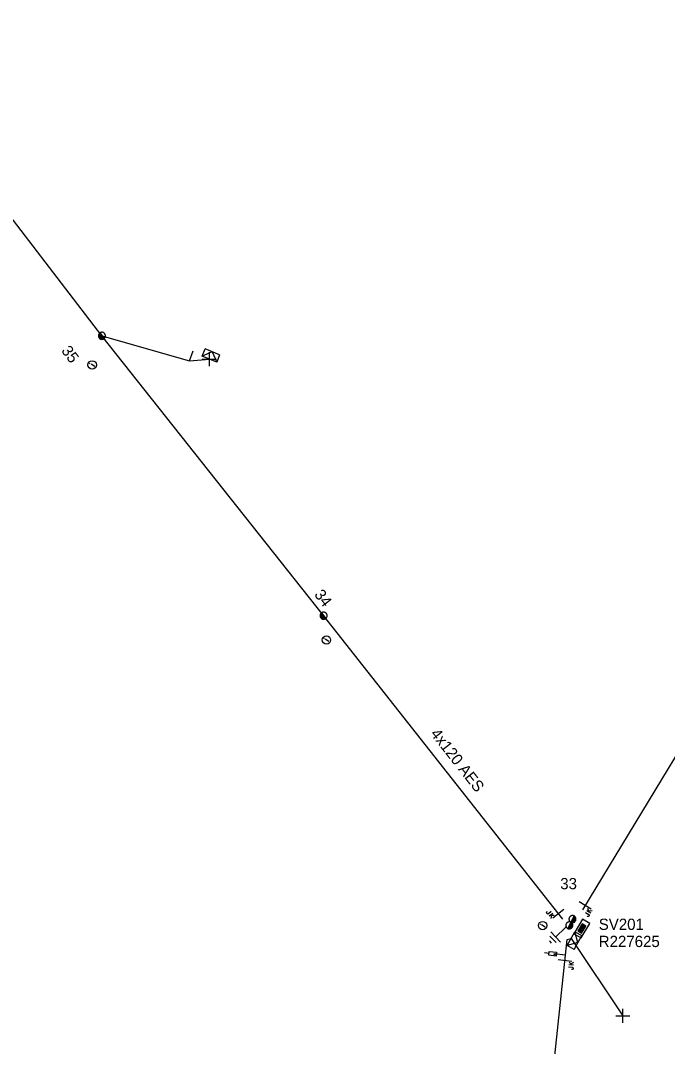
# Model space of a CAD drawing. Extents: x -544780 to -541582, y -1198995 to -1196551.
# Drawn here: x -543784.9 to -543727.4, y -1197085.7 to -1196994.5 of the extents above; entities that cross this region are included whole.
import ezdxf

# ---------------------------------------------------------------- set-up
doc = ezdxf.new("R2010")
doc.units = 0
for name, color, linetype in [('Vrstva 1', 7, 'Continuous'), ('Vrstva 10', 7, 'Continuous'), ('Vrstva 13', 7, 'Continuous'), ('Vrstva 14', 7, 'Continuous'), ('Vrstva 15', 7, 'Continuous'), ('Vrstva 16', 7, 'Continuous'), ('Vrstva 18', 7, 'Continuous'), ('Vrstva 2', 7, 'Continuous'), ('Vrstva 28', 7, 'Continuous'), ('Vrstva 29', 7, 'Continuous'), ('Vrstva 30', 7, 'Continuous'), ('Vrstva 31', 7, 'Continuous'), ('Vrstva 34', 7, 'Continuous'), ('Vrstva 36', 7, 'Continuous'), ('Vrstva 50', 7, 'Continuous'), ('Vrstva 51', 7, 'Continuous'), ('Vrstva 54', 7, 'Continuous'), ('Vrstva 59', 7, 'Continuous'), ('Vrstva 8', 7, 'Continuous'), ('Vrstva 9', 7, 'Continuous')]:
    doc.layers.add(name, color=color, linetype=linetype)

# ---------------------------------------------------------------- blocks, each defined once
blk = doc.blocks.new('NN440')
at = {"layer": 'Vrstva 2'}
for points in [[(0.63, 0), (0.63, 0.06), (0.62, 0.13), (0.6, 0.19), (0.58, 0.25), (0.55, 0.31), (0.51, 0.37), (0.47, 0.42), (0.42, 0.46), (0.37, 0.51), (0.32, 0.54), (0.26, 0.57), (0.2, 0.59), (0.13, 0.61), (0.07, 0.62), (0, 0.63), (-0.06, 0.62), (-0.13, 0.61), (-0.19, 0.59), (-0.26, 0.57), (-0.31, 0.54), (-0.37, 0.51), (-0.42, 0.46), (-0.47, 0.42), (-0.51, 0.37), (-0.54, 0.31), (-0.57, 0.25), (-0.6, 0.19), (-0.62, 0.13), (-0.63, 0.06), (-0.63, 0), (-0.63, -0.07), (-0.62, -0.14), (-0.6, -0.2), (-0.57, -0.26), (-0.54, -0.32), (-0.51, -0.37), (-0.47, -0.43), (-0.42, -0.47), (-0.37, -0.51), (-0.31, -0.55), (-0.26, -0.58), (-0.19, -0.6), (-0.13, -0.62), (-0.06, -0.63), (0, -0.63), (0.07, -0.63), (0.13, -0.62), (0.2, -0.6), (0.26, -0.58), (0.32, -0.55), (0.37, -0.51), (0.42, -0.47), (0.47, -0.43), (0.51, -0.37), (0.55, -0.32), (0.58, -0.26), (0.6, -0.2), (0.62, -0.14), (0.63, -0.07), (0.63, 0)], [(-0.63, 0), (0.63, 0)], [(-0.6, -0.18), (0.57, -0.18)], [(-0.51, -0.32), (0.5, -0.32)], [(-0.37, -0.47), (0.35, -0.47)]]:
    blk.add_lwpolyline(points, dxfattribs=at)
blk = doc.blocks.new('NN450')
at = {"layer": 'Vrstva 2'}
for points in [[(0, 0), (0, 0.07), (-0.01, 0.13), (-0.03, 0.19), (-0.05, 0.25), (-0.08, 0.31), (-0.12, 0.37), (-0.16, 0.42), (-0.21, 0.46), (-0.26, 0.51), (-0.31, 0.54), (-0.37, 0.57), (-0.43, 0.59), (-0.5, 0.61), (-0.56, 0.62), (-0.63, 0.62), (-0.69, 0.62), (-0.75, 0.61), (-0.82, 0.59), (-0.88, 0.57), (-0.94, 0.54), (-0.99, 0.51), (-1.04, 0.46), (-1.09, 0.42), (-1.13, 0.37), (-1.17, 0.31), (-1.2, 0.25), (-1.22, 0.19), (-1.24, 0.13), (-1.25, 0.07), (-1.25, 0), (-1.25, -0.07), (-1.24, -0.13), (-1.22, -0.19), (-1.2, -0.25), (-1.17, -0.31), (-1.13, -0.37), (-1.09, -0.42), (-1.04, -0.46), (-0.99, -0.51), (-0.94, -0.54), (-0.88, -0.57), (-0.82, -0.59), (-0.75, -0.61), (-0.69, -0.62), (-0.62, -0.63), (-0.56, -0.62), (-0.5, -0.61), (-0.43, -0.59), (-0.37, -0.57), (-0.31, -0.54), (-0.26, -0.51), (-0.21, -0.46), (-0.16, -0.42), (-0.12, -0.37), (-0.08, -0.31), (-0.05, -0.25), (-0.03, -0.19), (-0.01, -0.13), (0, -0.07), (0, 0)], [(1.25, 0), (1.25, 0.07), (1.24, 0.13), (1.22, 0.19), (1.2, 0.25), (1.17, 0.31), (1.13, 0.37), (1.09, 0.42), (1.04, 0.46), (0.99, 0.51), (0.94, 0.54), (0.88, 0.57), (0.82, 0.59), (0.75, 0.61), (0.69, 0.62), (0.62, 0.62), (0.56, 0.62), (0.5, 0.61), (0.43, 0.59), (0.37, 0.57), (0.31, 0.54), (0.26, 0.51), (0.21, 0.46), (0.16, 0.42), (0.12, 0.37), (0.08, 0.31), (0.05, 0.25), (0.03, 0.19), (0.01, 0.13), (0, 0.07), (0, 0), (0, -0.07), (0.01, -0.13), (0.03, -0.19), (0.05, -0.25), (0.08, -0.31), (0.12, -0.37), (0.16, -0.42), (0.21, -0.46), (0.26, -0.51), (0.31, -0.54), (0.37, -0.57), (0.43, -0.59), (0.5, -0.61), (0.56, -0.62), (0.63, -0.63), (0.69, -0.62), (0.75, -0.61), (0.82, -0.59), (0.88, -0.57), (0.94, -0.54), (0.99, -0.51), (1.04, -0.46), (1.09, -0.42), (1.13, -0.37), (1.17, -0.31), (1.2, -0.25), (1.22, -0.19), (1.24, -0.13), (1.25, -0.07), (1.25, 0)], [(-1.25, 0), (1.25, 0)], [(-1.23, -0.16), (-0.02, -0.16)], [(-1.16, -0.32), (-0.09, -0.32)], [(-1.03, -0.47), (-0.22, -0.47)], [(0.02, -0.16), (1.23, -0.16)], [(0.09, -0.32), (1.16, -0.32)], [(0.22, -0.47), (1.03, -0.47)]]:
    blk.add_lwpolyline(points, dxfattribs=at)
blk = doc.blocks.new('NN840')
at = {"layer": 'Vrstva 15'}
for points in [[(0.003, 0.619), (0.003, -0.631)], [(-0.745, -0.71), (-0.745, -0.66)], [(-0.73, -0.764), (-0.745, -0.71)], [(-0.657, -0.798), (-0.73, -0.764)], [(-0.627, -0.798), (-0.657, -0.798)], [(-0.558, -0.764), (-0.627, -0.798)], [(-0.538, -0.71), (-0.558, -0.764)], [(-0.538, -0.385), (-0.538, -0.71)], [(-0.332, -0.385), (-0.332, -0.798)], [(-0.332, -0.641), (-0.125, -0.385)], [(-0.263, -0.557), (-0.091, -0.798)]]:
    blk.add_lwpolyline(points, dxfattribs=at)
blk = doc.blocks.new('NN770')
at = {"layer": 'Vrstva 10'}
for p, q in [((0.002, 0.187), (0.002, 0.263)), ((0.002, -0.276), (0.002, 0.111))]:
    blk.add_line(p, q, dxfattribs=at)
blk.add_circle((0, -0.008), 0.375, dxfattribs=at)
blk = doc.blocks.new('NN800')
at = {"layer": 'Vrstva 1'}
for points in [[(-0.442, 0.442), (0.442, -0.442)], [(-0.442, -0.442), (0.442, 0.442)]]:
    blk.add_lwpolyline(points, dxfattribs=at)
blk = doc.blocks.new('NN820')
at = {"layer": 'Vrstva 13'}
for points in [[(-0.003, 0.004), (-0.003, -1.049)], [(-0.165, -0.813), (0.165, -0.813)], [(-0.165, -1.473), (-0.165, -0.813)], [(0.165, -0.813), (0.165, -1.473)], [(0.165, -1.473), (-0.165, -1.473)], [(-0.003, -1.049), (-0.062, -0.926)], [(-0.003, -1.049), (0.057, -0.926)], [(-0.003, -1.473), (-0.003, -1.871)]]:
    blk.add_lwpolyline(points, dxfattribs=at)
blk = doc.blocks.new('NN620')
at = {"layer": 'Vrstva 8'}
for points in [[(0.752, 0.004), (-0.748, 0.004)], [(-0.748, 0.004), (-0.748, -0.746)], [(0.752, -0.746), (0.752, 0.004)], [(-0.748, -0.746), (0.752, -0.746)], [(0.368, -0.18), (-0.376, -0.18)], [(-0.376, -0.18), (-0.376, -0.558)], [(-0.376, -0.558), (0.368, -0.558)], [(0.321, -0.227), (-0.329, -0.227)], [(-0.329, -0.227), (-0.329, -0.51)], [(-0.329, -0.51), (0.321, -0.51)], [(0.274, -0.274), (-0.281, -0.274)], [(-0.281, -0.274), (-0.281, -0.463)], [(-0.281, -0.463), (0.274, -0.463)], [(0.227, -0.321), (-0.234, -0.321)], [(-0.234, -0.321), (-0.234, -0.416)], [(-0.234, -0.416), (0.227, -0.416)], [(-0.193, -0.369), (0.185, -0.369)], [(0.227, -0.416), (0.227, -0.321)], [(0.274, -0.463), (0.274, -0.274)], [(0.321, -0.51), (0.321, -0.227)], [(0.368, -0.558), (0.368, -0.18)]]:
    blk.add_lwpolyline(points, dxfattribs=at)
blk = doc.blocks.new('NN630')
at = {"layer": 'Vrstva 9'}
for points in [[(-0.003, -0.7), (-0.703, 0)], [(-0.703, -0.7), (-0.703, 0), (0.697, 0), (0.697, -0.7)], [(-0.703, -0.7), (0.697, -0.7)], [(-0.003, -0.7), (0.697, 0)]]:
    blk.add_lwpolyline(points, dxfattribs=at)
blk = doc.blocks.new('NN810')
at = {"layer": 'Vrstva 14'}
for points in [[(0.004, -0.64), (0.004, -1.89)], [(0.629, -1.89), (-0.621, -1.89)], [(0.388, -2.2), (-0.399, -2.2)], [(0.004, -2.515), (-0.124, -2.515)], [(0.137, -2.515), (0.004, -2.515)]]:
    blk.add_lwpolyline(points, dxfattribs=at)
blk = doc.blocks.new('NN510')
at = {"layer": 'Vrstva 2'}
blk.add_lwpolyline([(0.001, 0.002), (0.001, 0.939)], dxfattribs=at)

msp = doc.modelspace()

# ---------------------------------------------------------------- linework, layer by layer
at = {"layer": 'Vrstva 1'}
msp.add_lwpolyline([(-543700.351, -1197016.243), (-543719.214, -1197047.592), (-543734.928, -1197073.555)], dxfattribs=at)
at = {"layer": 'Vrstva 50'}
for points in [[(-543736.683, -1197074.383), (-543757.94, -1197047.4), (-543777.639, -1197022.529), (-543792.02, -1197003.8), (-543812.04, -1196994.253)], [(-543775.44, -1197359.32), (-543772.569, -1197338.779), (-543766.769, -1197307.71), (-543762.65, -1197277.68), (-543758.39, -1197243.149), (-543754.189, -1197211.47), (-543748.549, -1197175.829), (-543744.639, -1197143.859), (-543740.249, -1197113.279), (-543736.44, -1197077.571), (-543736.293, -1197076.19)]]:
    msp.add_lwpolyline(points, dxfattribs=at)
at = {"layer": 'Vrstva 54'}
for points in [[(-543777.639, -1197022.529), (-543769.875, -1197024.752), (-543768.096, -1197024.607)], [(-543736.293, -1197076.19), (-543735.95, -1197076.102)]]:
    msp.add_lwpolyline(points, dxfattribs=at)
at = {"layer": 'Vrstva 59'}
msp.add_lwpolyline([(-543735.95, -1197076.102), (-543731.353, -1197082.956)], dxfattribs=at)

# ---------------------------------------------------------------- block references
at = {"layer": 'Vrstva 13', "xscale": 0.5}
for name, p, yscale, rotation in [('NN440', (-543777.64, -1197022.53), 0.5, -53.35139723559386), ('NN440', (-543757.939, -1197047.4), 0.49999999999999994, -52.526830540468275), ('NN450', (-543735.963, -1197074.647), 0.5000000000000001, 63.43494992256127)]:
    msp.add_blockref(name, p, dxfattribs=dict(at, yscale=yscale, rotation=rotation))
at = {"layer": 'Vrstva 13', "rotation": -22.150669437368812}
msp.add_blockref('NN510', (-543769.875, -1197024.752), dxfattribs=at)
at = {"layer": 'Vrstva 15', "rotation": -46.01377785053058}
msp.add_blockref('NN810', (-543735.962, -1197074.647), dxfattribs=at)
at = {"layer": 'Vrstva 16', "rotation": -96.08828334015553}
msp.add_blockref('NN820', (-543736.44, -1197077.571), dxfattribs=at)
at = {"layer": 'Vrstva 18'}
for p, rotation in [((-543737.077, -1197073.881), -51.79350003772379), ((-543734.712, -1197073.122), 58.81457770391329), ((-543736.495, -1197078.028), 83.67916393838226)]:
    msp.add_blockref('NN840', p, dxfattribs=dict(at, rotation=rotation))
at = {"layer": 'Vrstva 28', "rotation": 59.894999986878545}
msp.add_blockref('NN620', (-543735.314, -1197075.022), dxfattribs=at)
at = {"layer": 'Vrstva 31'}
for p, rotation in [((-543768.096, -1197024.607), 158.09686677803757), ((-543735.95, -1197076.102), 60.70559443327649)]:
    msp.add_blockref('NN630', p, dxfattribs=dict(at, rotation=rotation))
at = {"layer": 'Vrstva 34', "rotation": 45}
for p in [(-543768.096, -1197024.608), (-543731.353, -1197082.956)]:
    msp.add_blockref('NN800', p, dxfattribs=at)
at = {"layer": 'Vrstva 36'}
for p, rotation in [((-543778.518, -1197025.119), 58.51630274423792), ((-543757.702, -1197049.561), 58.516302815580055), ((-543738.482, -1197074.94), 58.51630274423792)]:
    msp.add_blockref('NN770', p, dxfattribs=dict(at, rotation=rotation))

# ---------------------------------------------------------------- texts
at = {"layer": 'Vrstva 14'}
for s, rotation, p in [('35', 306.649, (-543781.3, -1197023.864)), ('34', 307.473, (-543758.82, -1197045.542))]:
    msp.add_text(s, height=1, rotation=rotation, dxfattribs=at).set_placement(p)
msp.add_text('33', height=1, dxfattribs=at).set_placement((-543736.913, -1197071.716))
at = {"layer": 'Vrstva 29'}
msp.add_text('R227625', height=1, dxfattribs=at).set_placement((-543733.492, -1197076.851))
at = {"layer": 'Vrstva 30'}
msp.add_text('SV201', height=1, dxfattribs=at).set_placement((-543733.492, -1197075.33))
at = {"layer": 'Vrstva 51'}
msp.add_text('4x120 AES', height=1, rotation=308.103, dxfattribs=at).set_placement((-543748.5, -1197057.913))

doc.saveas('drawing.dxf')
